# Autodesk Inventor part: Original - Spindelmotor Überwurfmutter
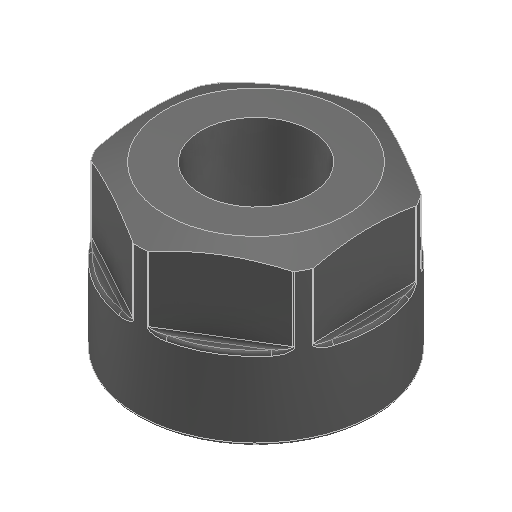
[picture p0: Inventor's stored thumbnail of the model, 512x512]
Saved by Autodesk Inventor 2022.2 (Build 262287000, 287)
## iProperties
Created: 2024-09
Part Number: Original - Spindelmotor Überwurfmutter
Material: Generico
Document SubType Name: Modeling
Designer: 18907419
Density: 1 g/cm^3
Appearance: Default
Author: 18907419
Revision Number: ANY
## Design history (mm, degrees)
feature "Verrundung1"
node "Solido1"
